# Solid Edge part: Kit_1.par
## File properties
Sűrűség: 0,000 kg/m^3
Pontosság: 0,990
Author: bmolnar
Last saved by: bmolnar
Revision: 78
Username: bmolnar
Dokumentum tartalom típus: 0
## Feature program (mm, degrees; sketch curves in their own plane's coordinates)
base feature "unnamed BaseFeature 1"
sketch for "Furat_1" plane through (-18.15, 18.15, 0) normal (1, 0, 0) x-axis (0, 0, -1)
  hole centre (0, -13.85) bore radius 2.067
hole "Furat_1" nominal diameter 5 finite  ThreadDepth = 5 mm; StartChamferOffset = 0.6 mm; StartChamferAngle = 45 deg
sketch for "Furat_2" plane through (-11, 6.7, 11) normal (0, 1, 0) x-axis (0, 0, -1)
  hole centre (0, 0) bore radius 2.067
hole "Furat_2" nominal diameter 5
sketch for "unnamed Hole 1" plane through (-11, 6.7, 11) normal (0, 1, 0) x-axis (0, 0, -1)
  hole centre (22, 0) bore radius 2.067
hole "unnamed Hole 1"
sketch for "unnamed Hole 2" plane through (-11, 6.7, 11) normal (0, 1, 0) x-axis (0, 0, -1)
  hole centre (22, -22) bore radius 2.067
hole "unnamed Hole 2"
sketch for "unnamed Hole 3" plane through (-11, 6.7, 11) normal (0, 1, 0) x-axis (0, 0, -1)
  hole centre (0, -22) bore radius 2.067
hole "unnamed Hole 3"
pattern "unnamed Pattern 1" of "Furat_2", "unnamed Hole 1", "unnamed Hole 2", "unnamed Hole 3"
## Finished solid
Body 1: solid body, 238 faces, 596 edges, 372 vertices, 2 internal voids.
  Faces by surface: plane 121, cylinder 54, swept 43, cone 16, torus 4
  Edges by curve: line 361, circle 135, spline 90, curve on surface 5, intersection 4, ellipse 1
Bounding box of the edges (mm; curved faces can reach further): 36.300 x 11.800 x 36.300, from (-18.15, 0, -18.15) to (18.15, 11.8, 18.15).
Cylindrical faces by radius (mm): R0.2 x18, R0.4246 x1, R0.4865 x1, R2.067 x5, R3.75 x2, R4 x4, R4.1 x12, R4.5 x1, R5.45 x2, R5.55 x2, R11.25 x6
Conical faces (half-angle, radius in mm at the cone's reference point): 0.5 deg R4.5 x4, 45 deg R2.317 x2, 45 deg R2.367 x2, 45 deg R2.667 x1, 45 deg R4.25 x2, 45 deg R4.65 x1, 45 deg R5.3 x2, 45 deg R5.35 x2
Toroidal faces (ring radius, tube radius in mm): R3.8 r0.2 x2, R4.4 r0.4 x2
Planar faces by outward normal: +x 5, +y 14, +z 13, -x 7, -y 3, -z 15, oblique 64
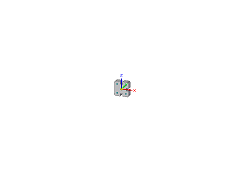
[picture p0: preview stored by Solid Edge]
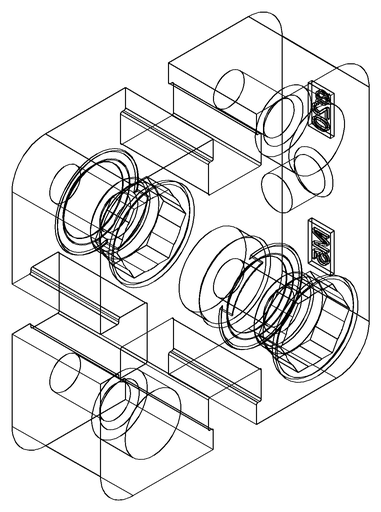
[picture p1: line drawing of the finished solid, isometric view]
